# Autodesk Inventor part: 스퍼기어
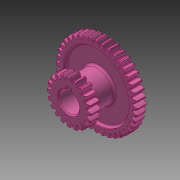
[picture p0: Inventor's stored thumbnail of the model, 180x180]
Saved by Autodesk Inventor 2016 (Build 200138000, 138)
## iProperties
Created: 2015-09
Part Number: 스퍼기어
Material: 강철, 연강
Document SubType Name: Modeling
Designer: mduedu
Density: 7.86 g/cm^3
Mass: 345.726 g
Surface Area: 225.641 cm^2
Volume: 43.9855 cm^3
Appearance: 분홍색
Author: mduedu
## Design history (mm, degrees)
sketch "스케치1"
  geometry: C1 r 38 at (0, 0); C2 r 40 at (0, 0); C3 r 35.5 at (0, 0); 1 further point
  constraints: 3 centre point, 3 coincident
  dimensions: "d0" = 76 diameter of C1; "d2" = 2 radial gap between concentric circles of C2 C1; "d3" = 71 diameter of C3 (computed from d0)
extrude "돌출1" new body sketch "스케치1" stored distance "d4" = 10; taper "d5" = 0 deg
sketch "스케치2"
  geometry: L1 (0, 35.5)-(0, -35.5); L2 (0, 0)-(40, 0); L3 (0, 0.57)-(39.996, 0.57); L4 (0, 1.57)-(39.969, 1.57); L5 (0, 2.07)-(39.946, 2.07); A1 r 35.5 centre (0, 0) between (0, 35.5) and (0, -35.5) reference; A2 r 40 centre (0, 0) between (40, 0) and (39.946, 2.07) reference; A3 r 9.234 centre (34.93, -7.149) between (39.996, 0.57) and (35.44, 2.07); A4 r 9.234 centre (34.93, 7.149) between (35.44, -2.07) and (39.996, -0.57); A5 r 40 centre (0, 0) between (39.996, -0.57) and (39.996, 0.57); A6 r 35.5 centre (0, 0) between (35.44, -2.07) and (35.44, 2.07); 4 further points
  constraints: 16 point on circle, 10 end point, 6 point on line, 4 centre point, 3 coincident, 3 parallel, 3 symmetric about line, 2 midpoint, 1 perpendicular, 1 vertical, 3 other
  dimensions: "d6" = 0.5 distance between parallel lines of L4 L5; "d8" = 1 distance between parallel lines of L3 L4; "d9" = 1.57 distance between parallel lines of L2 L4
extrude "돌출2" join sketch "스케치2" distance "d10" = 5; taper "d12" = 0 deg; dims "d11" = 5, "d13" = 0
fillet "모깎기1" dims "d17" = 0.5
chamfer "모따기1" distance "d21" = 1; stored, may be unused: second distance "d22" = 2, angle "d23" = 45 deg
sketch "스케치3"
  geometry: C1 r 32.5 at (0, 0); C2 r 15 at (0, 0); 1 further point
  constraints: 2 centre point, 2 coincident
  dimensions: "d27" = 65 diameter of C1; "d28" = 30 diameter of C2
extrude "돌출3" cut sketch "스케치3" distance "d29" = 3; taper "d30" = 0 deg
fillet "모깎기2" dims "d31" = 2
node "작업 평면2"
  node "작업 평면1"
sketch "스케치4"
  geometry: C1 r 15 at (0, 0) reference; 1 further point
extrude "돌출4" join sketch "스케치4" stored distance "d34" = 3; taper "d35" = 0 deg
sketch "스케치5"
  geometry: C1 r 17.5 at (0, 0); C2 r 20 at (0, 0); C3 r 22 at (0, 0); 1 further point
  constraints: 3 centre point, 3 coincident
  dimensions: "d36" = 40 diameter of C2; "d38" = 2 radial gap between concentric circles of C2 C3; "d39" = 35 diameter of C1 (= d36 - 2.5 x d38)
extrude "돌출6" join sketch "스케치5" distance "d46" = 10; taper "d47" = 0 deg
sketch "스케치6"
  geometry: L1 (0, 0)-(0, 22); L2 (-17.5, 0)-(17.5, 0); L3 (-0.57, 0)-(-0.57, 21.993); L4 (-1.57, 0)-(-1.57, 21.944); L5 (-2.07, 0)-(-2.07, 21.902); A1 r 22 centre (0, 0) between (0, 22) and (-0.57, 21.993) reference; A2 r 17.5 centre (0, 0) between (-17.5, 0) and (17.5, 0) reference; A3 r 9.431 centre (7.348, 16.868) between (-0.57, 21.993) and (-2.07, 17.377); A4 r 9.431 centre (-7.348, 16.868) between (2.07, 17.377) and (0.57, 21.993); A5 r 17.5 centre (0, 0) between (2.07, 17.377) and (-2.07, 17.377); A6 r 22 centre (0, 0) between (0.57, 21.993) and (-0.57, 21.993); 4 further points
  constraints: 16 point on circle, 10 end point, 5 point on line, 4 centre point, 3 coincident, 3 symmetric about line, 2 parallel, 2 perpendicular, 1 midpoint, 1 vertical, 3 other
  dimensions: "d40" = 0.5 distance between parallel lines of L4 L5; "d42" = 1 distance between parallel lines of L3 L4; "d43" = 1.57 distance between parallel lines of L1 L4
extrude "돌출5" join sketch "스케치6" distance "d44" = 10; taper "d45" = 0 deg
fillet "모깎기3" dims "d48" = 0.5
chamfer "모따기2" distance "d49" = 1; stored, may be unused: second distance "d50" = 2, angle "d51" = 45 deg
sketch "스케치7"
  geometry: C1 r 10 at (0, 0); 1 further point
  constraints: 1 centre point, 1 coincident
  dimensions: "d55" = 20 diameter of C1
extrude "돌출7" cut sketch "스케치7" stored distance "d56" = 10; taper "d57" = 0 deg
sketch "스케치8"
  geometry: L1 (-9.539, -3)-(-12.8, -3); L2 (-12.8, -3)-(-12.8, 3); L3 (-12.8, 3)-(-9.539, 3); L4 (-9.539, 3)-(-9.539, -3); A1 r 10 centre (0, 0) between (-9.539, -3) and (-9.539, 3) reference; 2 further points
  constraints: 8 end point, 3 point on circle, 2 parallel, 1 horizontal, 1 horizontal alignment, 1 perpendicular
  dimensions: "d58" = 6 distance of L1.end L2.end; "d60" = 22.8 distance from line of point (10, 0) L2
extrude "돌출8" cut sketch "스케치8" stored distance "d61" = 10; taper "d62" = 0 deg
chamfer "모따기3" distance "d63" = 1; stored, may be unused: second distance "d64" = 2, angle "d65" = 45 deg
fillet "모깎기4" dims "d66" = 2
node "솔리드1"
pattern_circular "원형 패턴3" dims "d25" = 360 deg
mirror "대칭1"
pattern_circular "원형 패턴4" dims "d53" = 360 deg
other parameters: "d32" = 5, "d33" = 42
